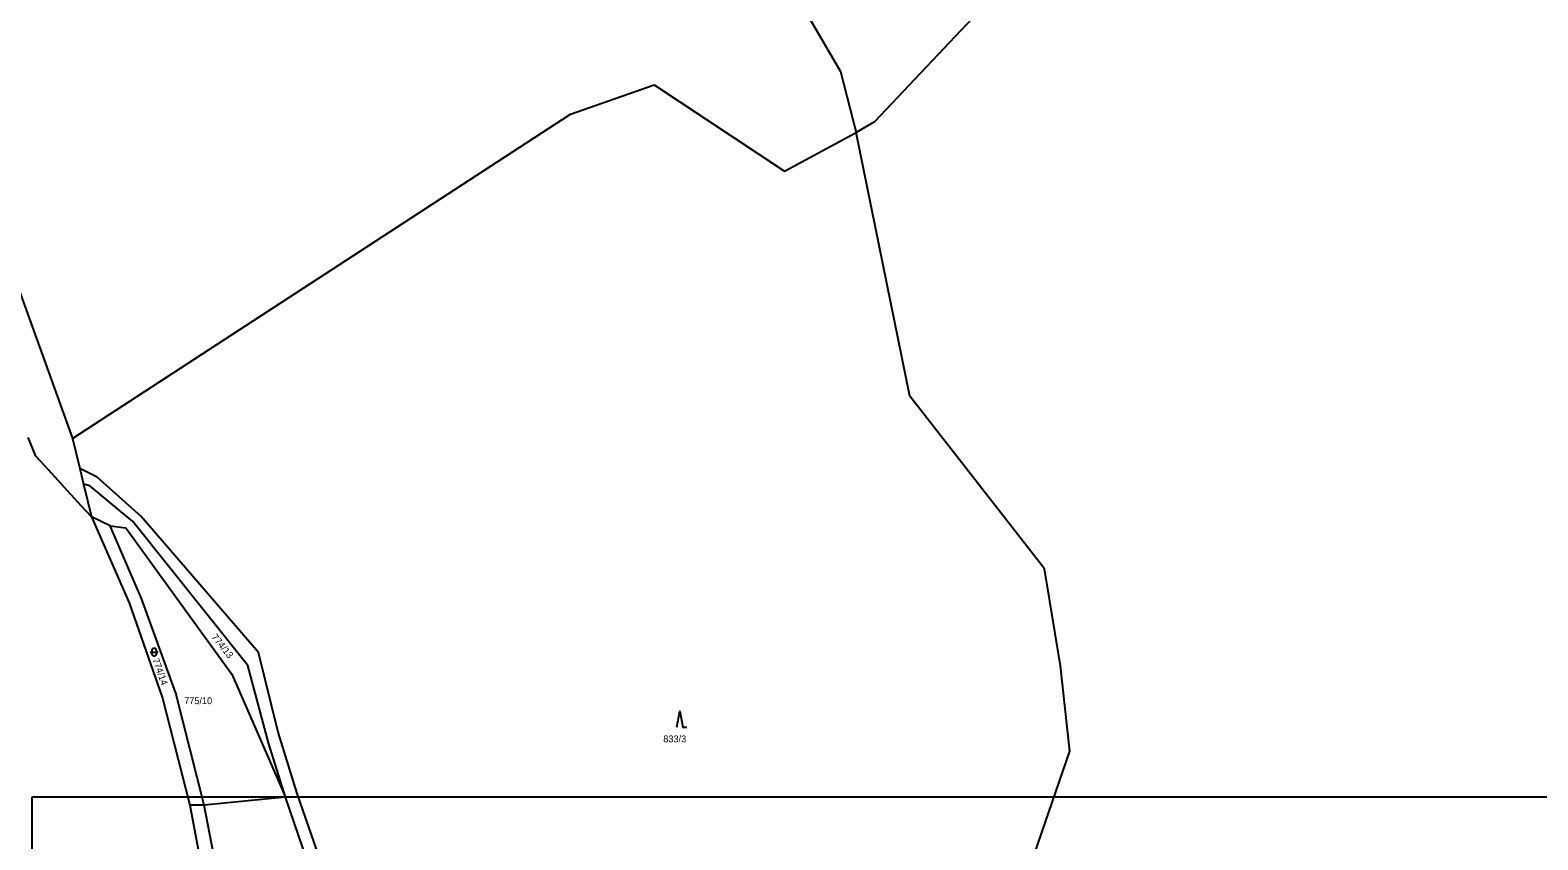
# Model space of a CAD drawing. Extents: x -801907 to -800293, y -1016964 to -1015684.
# Drawn here: x -801306.6 to -800931.6, y -1016334.3 to -1016132.8 of the extents above; entities that cross this region are included whole.
import ezdxf

# ---------------------------------------------------------------- set-up
doc = ezdxf.new("R2010")
doc.units = 0
for name, color, linetype in [('Default', 7, 'Continuous'), ('KN_HRANICE', 7, 'Continuous'), ('KN_KULTURY', 7, 'Continuous'), ('KN_PARCELY', 7, 'Continuous'), ('LEGENDA', 7, 'Continuous')]:
    doc.layers.add(name, color=color, linetype=linetype)

# ---------------------------------------------------------------- blocks, each defined once
blk = doc.blocks.new('308')
at = {"layer": 'Default'}
blk.add_lwpolyline([(-0.75, 0), (0, 4), (0.75, 0), (1.75, 0)], dxfattribs=at)
blk = doc.blocks.new('316')
at = {"layer": 'Default'}
for points in [[(-1, 1), (0.27, 1), (1, 1)], [(-0.5, 1.5), (-0.4, 1.79), (-0.15, 1.97), (0.16, 1.97), (0.41, 1.79), (0.51, 1.5), (0.51, 0.5), (0.41, 0.21), (0.16, 0.03), (-0.15, 0.03), (-0.4, 0.21), (-0.5, 0.5), (-0.5, 1.5)]]:
    blk.add_lwpolyline(points, dxfattribs=at)

msp = doc.modelspace()

# ---------------------------------------------------------------- linework, layer by layer
at = {"layer": 'KN_HRANICE'}
for p, q in [((-801119.11, -1016118.95), (-801105.07, -1016143.14)), ((-801072.19, -1016129.88), (-801096.58, -1016155.67)), ((-801105.07, -1016143.14), (-801101.16, -1016158.27)), ((-801327.07, -1016148.63), (-801296.08, -1016234.39)), ((-801172.18, -1016153.77), (-801151.44, -1016146.42)), ((-801151.44, -1016146.42), (-801118.95, -1016167.92)), ((-801296.08, -1016234.39), (-801172.18, -1016153.77)), ((-801096.58, -1016155.67), (-801101.16, -1016158.27)), ((-801118.95, -1016167.92), (-801101.16, -1016158.27)), ((-801087.8, -1016223.87), (-801101.16, -1016158.27)), ((-801054.29, -1016266.88), (-801087.8, -1016223.87)), ((-801305.22, -1016238.85), (-801307.14, -1016234.16)), ((-801296.08, -1016234.39), (-801294.26, -1016241.91)), ((-801302.16, -1016242.17), (-801305.22, -1016238.85)), ((-801296.43, -1016248.4), (-801302.16, -1016242.17)), ((-801289.98, -1016244.05), (-801294.26, -1016241.91)), ((-801294.26, -1016241.91), (-801293.32, -1016245.8)), ((-801293.32, -1016245.8), (-801291.35, -1016253.92)), ((-801291.77, -1016246.21), (-801293.32, -1016245.8)), ((-801281.12, -1016255.04), (-801291.77, -1016246.21)), ((-801278.99, -1016253.83), (-801289.98, -1016244.05)), ((-801293.82, -1016251.23), (-801296.43, -1016248.4)), ((-801291.35, -1016253.92), (-801293.82, -1016251.23)), ((-801286.71, -1016256.11), (-801291.35, -1016253.92)), ((-801291.35, -1016253.92), (-801281.96, -1016275.28)), ((-801249.86, -1016287.66), (-801278.99, -1016253.83)), ((-801286.71, -1016256.11), (-801282.82, -1016256.61)), ((-801278.95, -1016274.23), (-801286.71, -1016256.11)), ((-801282.82, -1016256.61), (-801256.44, -1016293.08)), ((-801252.47, -1016290.85), (-801281.12, -1016255.04)), ((-801050.29, -1016291), (-801054.29, -1016266.88)), ((-801281.96, -1016275.28), (-801273.73, -1016298.99)), ((-801270.4, -1016297.77), (-801278.95, -1016274.23)), ((-801244.9, -1016307.46), (-801249.86, -1016287.66)), ((-801247.34, -1016310.15), (-801252.47, -1016290.85)), ((-801047.99, -1016312.24), (-801050.29, -1016291)), ((-801256.44, -1016293.08), (-801243.11, -1016323.66)), ((-801273.73, -1016298.99), (-801266.91, -1016325.63)), ((-801263.32, -1016325.64), (-801270.4, -1016297.77)), ((-801240.17, -1016322.77), (-801244.9, -1016307.46)), ((-801243.11, -1016323.66), (-801247.34, -1016310.15)), ((-801061.14, -1016350.27), (-801047.99, -1016312.24)), ((-801263.32, -1016325.64), (-801266.91, -1016325.63)), ((-801266.91, -1016325.63), (-801262.33, -1016349.67)), ((-801243.11, -1016323.66), (-801263.32, -1016325.64)), ((-801256.32, -1016362.14), (-801263.32, -1016325.64)), ((-801235.95, -1016344.57), (-801243.11, -1016323.66)), ((-801232.53, -1016344.87), (-801240.17, -1016322.77))]:
    msp.add_line(p, q, dxfattribs=at)
at = {"layer": 'LEGENDA'}
msp.add_lwpolyline([(-801306.12, -1016323.56), (-800712.12, -1016323.56), (-800712.12, -1016743.56), (-801306.12, -1016743.56)], close=True, dxfattribs=at)

# ---------------------------------------------------------------- block references
at = {"layer": 'KN_KULTURY'}
for name, p in [('316', (-801275.77, -1016288.57)), ('308', (-801145, -1016306.26))]:
    msp.add_blockref(name, p, dxfattribs=at)

# ---------------------------------------------------------------- texts
at = {"layer": 'KN_PARCELY'}
for s, rotation, p in [('774/13', 308.939, (-801261.63, -1016283.87)), ('774/14', 289.516, (-801276.25, -1016289.41))]:
    msp.add_text(s, height=1.7, rotation=rotation, dxfattribs=at).set_placement(p)
for s, p in [('775/10', (-801268.3, -1016300.5)), ('833/3', (-801149.13, -1016310))]:
    msp.add_text(s, height=1.7, dxfattribs=at).set_placement(p)

doc.saveas('drawing.dxf')
